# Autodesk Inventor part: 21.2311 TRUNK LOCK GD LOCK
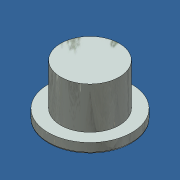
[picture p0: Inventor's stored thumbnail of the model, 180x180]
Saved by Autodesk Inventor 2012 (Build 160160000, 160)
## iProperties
Created: 2014-09
Part Number: 21.2311 TRUNK LOCK GD LOCK
Material: Steel
Document SubType Name: Modeling
Designer: Admin
Density: 7.85 g/cm^3
Mass: 10.8393 g
Surface Area: 8.83047 cm^2
Volume: 1.38081 cm^3
Author: Admin
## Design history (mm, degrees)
feature "Base1"
body "Solid1"
